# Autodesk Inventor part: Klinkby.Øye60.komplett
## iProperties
Created: 2009-07
Part Number: Klinkby.Øye60.komplett
Document SubType Name: Modeling
Designer: TB
Mass: 606.879 g
Surface Area: 993.651 cm^2
Volume: 606.879 cm^3
Density: 1 g/cm^3
Author: TB
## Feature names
1. Hole1
